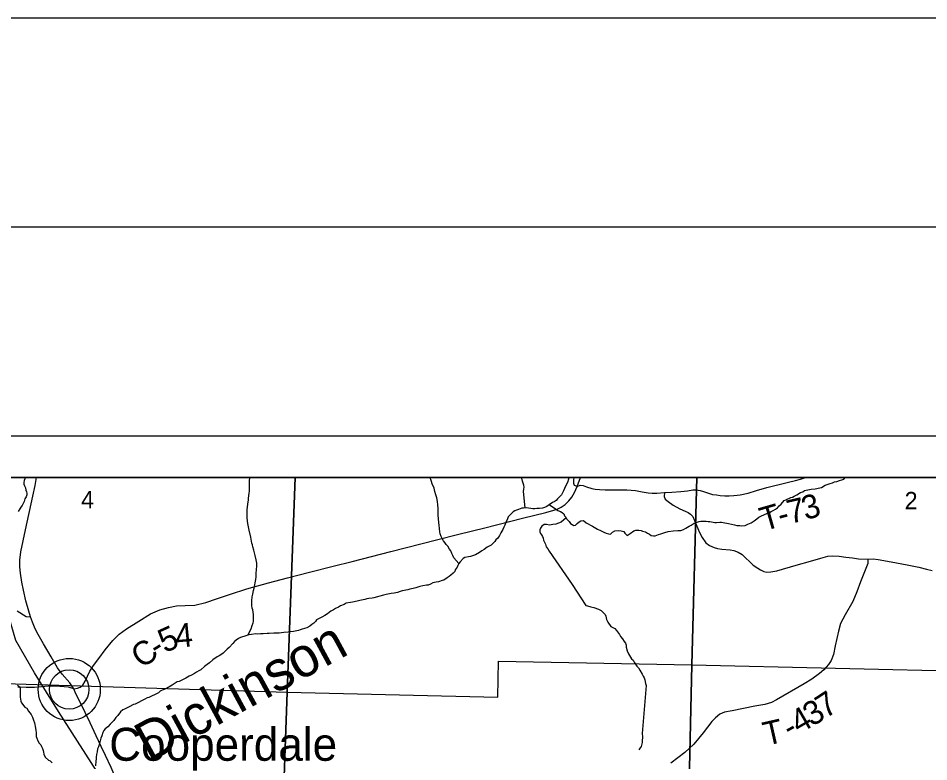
# Model space of a CAD drawing. Extents: x 0 to 34, y 0 to 22.
# Drawn here: x 3.454 to 5.636, y 20.219 to 22 of the extents above; entities that cross this region are included whole.
import ezdxf

# ---------------------------------------------------------------- set-up
doc = ezdxf.new("R2010")
doc.units = 0
for name, color, linetype in [('GM_X_Corporation', 7, 'Continuous'), ('GM_X_County_Road', 7, 'Continuous'), ('GM_X_County_Road_Text', 7, 'Continuous'), ('GM_X_Minor_River', 7, 'Continuous'), ('GM_X_Minor_River_Text', 7, 'Continuous'), ('GM_X_Rail_Line', 7, 'Continuous'), ('GM_X_Section_Text', 7, 'Continuous'), ('GM_X_State_Route', 7, 'Continuous'), ('GM_X_Township_Road', 7, 'Continuous'), ('GM_X_Township_Road_Text', 7, 'Continuous'), ('GM_X_Unincorporated', 7, 'Continuous'), ('GM_X_Unincorporated_Location', 7, 'Continuous'), ('GM_X_Unincorporated_Text', 7, 'Continuous'), ('SH_Border', 7, 'Continuous'), ('SH_Cut_Line', 7, 'Continuous'), ('SH_Data', 7, 'Continuous')]:
    doc.layers.add(name, color=color, linetype=linetype)

msp = doc.modelspace()

# ---------------------------------------------------------------- linework, layer by layer
at = {"layer": 'GM_X_Corporation'}
for points in [[(8.9, 20.9), (2.1, 20.9), (2.1, 16.4477), (2.1182, 16.4474), (2.1176, 16.4327), (2.1175, 16.4298), (2.1166, 16.4244), (2.1155, 16.4201), (2.2605, 16.4147), (2.3623, 16.41), (2.7707, 16.392), (3.0057, 16.3809), (3.6165, 16.3686), (3.7537, 16.3728), (3.9899, 16.3631), (4.4958, 16.358), (4.9914, 16.3477), (5.6931, 16.3352)], [(7.1302, 20.9), (2.2795, 20.9), (2.2346, 20.0021), (2.2301, 19.7293), (2.2185, 19.3474), (2.2174, 19.3106), (2.2173, 19.3051), (2.2163, 19.2747), (2.2155, 19.2474), (2.2151, 19.2353), (2.2075, 18.9201), (2.2042, 18.8835), (2.2038, 18.8576), (2.1995, 18.7384), (2.1894, 18.4715)]]:
    msp.add_lwpolyline(points, dxfattribs=at)
for points in [[(4.1178, 20.9), (3.125, 20.9), (3.1077, 20.4159), (4.0987, 20.3855)], [(5.08, 20.9), (4.1178, 20.9), (4.0987, 20.3855), (4.6031, 20.3739), (4.6046, 20.4596), (5.0677, 20.4508)], [(6.1094, 20.9), (5.08, 20.9), (5.0677, 20.4508), (6.1008, 20.4274)], [(4.0987, 20.3855), (4.6031, 20.3739), (4.6046, 20.4596), (5.0677, 20.4508), (5.0447, 19.4257), (4.5747, 19.4359), (4.5724, 19.3635), (4.0627, 19.3751)], [(6.1008, 20.4274), (6.0762, 19.405), (5.0447, 19.4257), (5.0677, 20.4508)], [(3.1077, 20.4159), (4.0987, 20.3855), (4.0627, 19.3751), (3.063, 19.4039)]]:
    msp.add_lwpolyline(points, close=True, dxfattribs=at)
at = {"layer": 'GM_X_County_Road'}
for points in [[(3.5871, 20.3938), (3.5961, 20.3949), (3.6021, 20.3975), (3.6084, 20.4028), (3.6144, 20.4123), (3.6257, 20.4357), (3.6345, 20.4493), (3.6474, 20.4663), (3.6625, 20.4868), (3.6808, 20.5097), (3.6959, 20.5248), (3.7136, 20.5374), (3.7426, 20.5561), (3.7711, 20.5731), (3.793, 20.5833), (3.814, 20.5887), (3.8335, 20.5921), (3.8543, 20.5933), (3.8772, 20.5941), (3.9036, 20.6005), (3.9288, 20.6093), (3.9629, 20.6203), (4.0014, 20.6329), (4.0538, 20.6478), (4.0994, 20.6593), (4.1518, 20.6729), (4.2084, 20.6873), (4.2541, 20.6984), (4.347, 20.7225), (4.4564, 20.7505), (4.5101, 20.7638), (4.5722, 20.7795), (4.6624, 20.8025), (4.7182, 20.8163), (4.7371, 20.8214), (4.745, 20.8238), (4.7546, 20.8288), (4.7649, 20.8355), (4.7735, 20.8439), (4.7804, 20.853), (4.7867, 20.8642), (4.7929, 20.8786), (4.8016, 20.8998), (4.8017, 20.9)], [(3.4517, 20.5803), (3.4734, 20.5669), (3.4834, 20.566)]]:
    msp.add_lwpolyline(points, dxfattribs=at)
at = {"layer": 'GM_X_Minor_River'}
for points in [[(3.4717, 20.9), (3.4701, 20.8967), (3.4682, 20.8925), (3.4678, 20.8876), (3.4678, 20.8838), (3.4694, 20.8796), (3.4716, 20.875)], [(4.004, 20.5221), (4.0118, 20.5371), (4.0148, 20.5451), (4.0167, 20.5516), (4.0174, 20.5553), (4.0178, 20.5607), (4.0178, 20.5652), (4.0174, 20.572), (4.0166, 20.5774), (4.0158, 20.583), (4.0147, 20.5872), (4.0139, 20.5933), (4.0135, 20.5982), (4.0135, 20.6047), (4.0146, 20.6138), (4.0161, 20.6206), (4.018, 20.6293), (4.0195, 20.635), (4.0206, 20.643), (4.0221, 20.6479), (4.0232, 20.6559), (4.0239, 20.6616), (4.0243, 20.6703), (4.025, 20.6798), (4.0254, 20.6874), (4.0254, 20.6946), (4.0242, 20.7026), (4.0219, 20.7132), (4.0188, 20.7257), (4.0158, 20.7337), (4.0154, 20.739), (4.0138, 20.7428), (4.0127, 20.747), (4.0112, 20.7572), (4.0073, 20.7739), (4.0058, 20.7815), (4.0042, 20.7898), (4.0031, 20.7955), (4.0023, 20.8042), (4.0023, 20.8111), (4.0026, 20.8221), (4.0034, 20.83), (4.0048, 20.8414), (4.0056, 20.8456), (4.006, 20.8505), (4.0074, 20.8623), (4.0078, 20.8668), (4.0082, 20.8718), (4.0085, 20.8839), (4.0085, 20.8915), (4.0092, 20.9)], [(4.51, 20.6936), (4.4978, 20.7076), (4.4951, 20.7133), (4.4929, 20.7175), (4.4902, 20.7243), (4.4871, 20.7284), (4.4833, 20.7353), (4.4795, 20.7391), (4.4761, 20.7444), (4.4727, 20.7485), (4.4696, 20.7538), (4.4677, 20.7584), (4.4654, 20.7652), (4.4639, 20.7694), (4.4631, 20.7777), (4.4623, 20.7861), (4.4616, 20.7914), (4.4608, 20.8013), (4.4604, 20.8088), (4.46, 20.8195), (4.46, 20.8259), (4.4592, 20.8346), (4.4584, 20.8422), (4.4568, 20.851), (4.4546, 20.8585), (4.4523, 20.8665), (4.4503, 20.8741), (4.4461, 20.8847), (4.4439, 20.8904), (4.4427, 20.8949), (4.4406, 20.9)], [(4.772, 20.9), (4.772, 20.8997), (4.7724, 20.8956), (4.7701, 20.888), (4.7656, 20.8788), (4.7629, 20.8739), (4.7607, 20.8682), (4.7581, 20.8629), (4.7558, 20.8587), (4.7524, 20.8549), (4.746, 20.8488), (4.7433, 20.845), (4.7384, 20.842), (4.7339, 20.8397), (4.7263, 20.8348), (4.7203, 20.8306), (4.715, 20.8283), (4.7104, 20.8268), (4.7028, 20.826), (4.6968, 20.8256), (4.6915, 20.8252), (4.6869, 20.8252), (4.6824, 20.8259), (4.671, 20.8271), (4.6649, 20.8267), (4.6604, 20.8263), (4.6528, 20.8236), (4.6479, 20.8217), (4.6437, 20.8198), (4.6396, 20.8175), (4.6328, 20.8107), (4.6283, 20.8054), (4.626, 20.8008), (4.6245, 20.797), (4.6226, 20.7932), (4.6196, 20.7856), (4.6177, 20.7811), (4.6151, 20.7754), (4.6128, 20.7716), (4.6106, 20.7674), (4.6072, 20.7609), (4.603, 20.7548), (4.5985, 20.7503), (4.5958, 20.7465), (4.5913, 20.7415), (4.5871, 20.7377), (4.5822, 20.7351), (4.5777, 20.7328), (4.5701, 20.7271), (4.5648, 20.724), (4.5592, 20.7202), (4.5493, 20.7149), (4.5425, 20.7126), (4.5376, 20.7107), (4.5327, 20.7099), (4.5243, 20.7084), (4.5202, 20.7057), (4.5126, 20.6981), (4.51, 20.6936)], [(4.6688, 20.8269), (4.6648, 20.8665), (4.6656, 20.8718), (4.6659, 20.8768), (4.6652, 20.8813), (4.664, 20.8866), (4.6625, 20.8912), (4.6609, 20.8984), (4.6604, 20.9)], [(5.3541, 20.8717), (5.3636, 20.8728), (5.3745, 20.8755), (5.3787, 20.8763), (5.3878, 20.8812), (5.3999, 20.8854), (5.4048, 20.8869), (5.4097, 20.8892), (5.4158, 20.8907), (5.4219, 20.8927), (5.4272, 20.8946), (5.4321, 20.8961), (5.4354, 20.9)], [(3.4716, 20.875), (3.4724, 20.8697), (3.4736, 20.8659), (3.4743, 20.8621), (3.4747, 20.8583), (3.4728, 20.8534), (3.4698, 20.8488), (3.468, 20.8424), (3.4657, 20.8375), (3.4631, 20.8329), (3.4604, 20.8287), (3.4582, 20.8249), (3.4536, 20.8181)], [(4.7266, 20.8349), (4.7411, 20.8245), (4.7468, 20.8208), (4.7533, 20.8181), (4.7574, 20.8158), (4.7612, 20.8128), (4.7631, 20.8083), (4.7662, 20.8045), (4.7688, 20.8003), (4.7738, 20.7942), (4.7776, 20.7901), (4.7814, 20.7871), (4.7852, 20.7852), (4.789, 20.7856), (4.7931, 20.7897), (4.798, 20.7935), (4.8022, 20.7962), (4.8086, 20.797), (4.8151, 20.7917), (4.8299, 20.783), (4.8417, 20.7762), (4.8493, 20.7728), (4.8568, 20.769), (4.8629, 20.7663), (4.8682, 20.7652), (4.8728, 20.7645), (4.8777, 20.769), (4.8834, 20.7721), (4.8917, 20.7728), (4.8985, 20.7721), (4.9053, 20.7706), (4.9076, 20.7664), (4.9129, 20.7611), (4.9201, 20.7661), (4.9288, 20.7718), (4.9338, 20.7741), (4.9413, 20.7741), (4.9463, 20.7726), (4.9501, 20.7714), (4.9569, 20.7696), (4.9618, 20.7665), (4.9664, 20.7639), (4.9705, 20.7612), (4.9762, 20.7601), (4.9804, 20.7605), (4.988, 20.7635), (4.9936, 20.7651), (4.9982, 20.7666), (5.0031, 20.7681), (5.0111, 20.7704), (5.0232, 20.772), (5.0345, 20.7731), (5.0417, 20.7731), (5.0478, 20.7754), (5.0535, 20.7785), (5.0618, 20.783), (5.0663, 20.7861), (5.0739, 20.7907), (5.0853, 20.7945), (5.0898, 20.7949), (5.094, 20.7952), (5.1027, 20.7949), (5.1072, 20.7945), (5.1114, 20.7945), (5.119, 20.7926), (5.1232, 20.7919), (5.1273, 20.7919), (5.1349, 20.7927), (5.1391, 20.7931), (5.1432, 20.7919), (5.1558, 20.7901), (5.1705, 20.7867), (5.1759, 20.7852), (5.1827, 20.7848), (5.1872, 20.7844), (5.1956, 20.7852), (5.202, 20.7879), (5.2103, 20.7913), (5.2171, 20.7959), (5.2239, 20.8012), (5.2285, 20.8046), (5.233, 20.8073), (5.2421, 20.8111), (5.2481, 20.8138), (5.2542, 20.8161), (5.2584, 20.8183), (5.2633, 20.821), (5.2686, 20.8237), (5.2731, 20.8275), (5.2773, 20.8317), (5.2818, 20.8362), (5.2894, 20.8446), (5.2935, 20.8465), (5.3049, 20.8518), (5.309, 20.8526), (5.3136, 20.8553), (5.32, 20.8587), (5.3287, 20.8636), (5.334, 20.8659), (5.3382, 20.8686), (5.3541, 20.8717)], [(4.7669, 20.8033), (4.7548, 20.7927), (4.7484, 20.7904), (4.7424, 20.7885), (4.7348, 20.7873), (4.7268, 20.7858), (4.7196, 20.7873), (4.7143, 20.7877), (4.709, 20.7831), (4.7056, 20.7789), (4.7041, 20.7744), (4.7038, 20.7698), (4.7053, 20.766), (4.7079, 20.7622), (4.7102, 20.7585), (4.7118, 20.7547), (4.7125, 20.7501), (4.7141, 20.7463), (4.7175, 20.7399), (4.7194, 20.7338), (4.7232, 20.7289), (4.7262, 20.7236), (4.7814, 20.6436), (4.8142, 20.5936), (4.8179, 20.5921), (4.8263, 20.5898), (4.8335, 20.5883), (4.8445, 20.5849), (4.8506, 20.5815), (4.8551, 20.5777), (4.8601, 20.5721), (4.862, 20.5679), (4.8639, 20.5595), (4.8666, 20.5535), (4.8742, 20.5432), (4.8833, 20.538), (4.8875, 20.5338), (4.892, 20.5273), (4.8947, 20.5236), (4.8974, 20.519), (4.9023, 20.5133), (4.9057, 20.5073), (4.9095, 20.5027), (4.9107, 20.4985), (4.9111, 20.4932), (4.913, 20.4849), (4.9164, 20.4773), (4.9233, 20.4659), (4.9271, 20.4622), (4.9297, 20.4572), (4.9366, 20.4481), (4.9404, 20.4436), (4.9434, 20.4387), (4.9488, 20.4288), (4.9511, 20.4243), (4.9537, 20.4197), (4.9556, 20.4155), (4.9572, 20.4064), (4.9583, 20.4019), (4.9492, 20.2865), (4.9496, 20.2789), (4.9492, 20.2687), (4.9489, 20.2649), (4.9466, 20.2558), (4.944, 20.252), (4.941, 20.2478)], [(4.51, 20.6936), (4.507, 20.6894), (4.5058, 20.6848), (4.5013, 20.6784), (4.4998, 20.6746), (4.496, 20.6704), (4.4904, 20.6662), (4.4862, 20.6624), (4.4817, 20.6594), (4.4741, 20.6541), (4.4699, 20.6529), (4.4608, 20.6499), (4.4552, 20.6491), (4.4476, 20.6472), (4.4415, 20.6445), (4.4359, 20.6422), (4.4321, 20.6418), (4.4234, 20.6407), (4.4165, 20.6388), (4.4071, 20.6353), (4.4003, 20.6342), (4.3927, 20.6327), (4.3874, 20.6308), (4.3741, 20.6281), (4.3692, 20.6265), (4.3624, 20.6246), (4.3548, 20.6231), (4.3476, 20.622), (4.3355, 20.6197), (4.3291, 20.6181), (4.3204, 20.6155), (4.3147, 20.6139), (4.3064, 20.6116), (4.3022, 20.6109), (4.2939, 20.6101), (4.2893, 20.6089), (4.2848, 20.6078), (4.2723, 20.6055), (4.2658, 20.604), (4.2549, 20.6009), (4.2499, 20.6005), (4.2401, 20.5986), (4.2348, 20.5959), (4.2265, 20.5925), (4.2212, 20.5895), (4.214, 20.586), (4.2094, 20.583), (4.2034, 20.5796), (4.1989, 20.5762), (4.1947, 20.5731), (4.1886, 20.5697), (4.1811, 20.5651), (4.1735, 20.5613), (4.1686, 20.559), (4.166, 20.5552), (4.1622, 20.551), (4.1576, 20.548), (4.1527, 20.5438), (4.1455, 20.5396), (4.1342, 20.537), (4.1296, 20.5347), (4.1255, 20.5335), (4.1175, 20.5316), (4.1134, 20.5309), (4.1043, 20.5301), (4.1005, 20.5297), (4.0903, 20.5285), (4.0796, 20.5274), (4.0706, 20.527), (4.0668, 20.527), (4.0554, 20.5266), (4.0505, 20.5262), (4.0406, 20.5258), (4.0349, 20.5254), (4.0274, 20.525), (4.0232, 20.5254), (4.0126, 20.5238), (4.0065, 20.5227), (3.999, 20.5208), (3.9865, 20.5166), (3.9815, 20.5143), (3.9763, 20.5105), (3.9721, 20.5071), (3.9683, 20.5025), (3.9596, 20.493), (3.9547, 20.4885), (3.9491, 20.4835), (3.9449, 20.4793), (3.9392, 20.4751), (3.9351, 20.4729), (3.9309, 20.4702), (3.9203, 20.463), (3.912, 20.4561), (3.9067, 20.4516), (3.9007, 20.447), (3.8916, 20.4394), (3.8867, 20.4367), (3.8814, 20.4333), (3.8761, 20.4303), (3.8689, 20.4268), (3.8632, 20.4238)], [(3.8632, 20.4238), (3.8553, 20.4192), (3.8398, 20.4112), (3.8352, 20.4101), (3.8231, 20.4021), (3.8091, 20.3945), (3.8038, 20.3918), (3.7989, 20.3907), (3.7944, 20.388), (3.7902, 20.3842), (3.7807, 20.3796), (3.7747, 20.377), (3.7667, 20.3728), (3.763, 20.3724), (3.7577, 20.369), (3.7342, 20.3572), (3.73, 20.356), (3.7198, 20.3503), (3.7085, 20.345), (3.7043, 20.3435), (3.699, 20.3385), (3.6926, 20.3302), (3.6881, 20.3248), (3.6828, 20.318), (3.6741, 20.3093), (3.6688, 20.3028), (3.6624, 20.2975), (3.659, 20.2937), (3.6567, 20.2891), (3.6545, 20.2811), (3.6522, 20.2758), (3.6503, 20.2694), (3.6488, 20.2637), (3.6477, 20.2599), (3.6462, 20.2546), (3.6443, 20.25), (3.6428, 20.2428), (3.6417, 20.2367), (3.641, 20.2303), (3.6406, 20.2261), (3.6399, 20.2204), (3.6388, 20.209)], [(3.4526, 20.4022), (3.4567, 20.3996), (3.4583, 20.3954), (3.4583, 20.3798), (3.4587, 20.3734), (3.4602, 20.3643), (3.4618, 20.3601), (3.4701, 20.3499), (3.4743, 20.3472), (3.4789, 20.3404), (3.485, 20.3324), (3.488, 20.3256)], [(3.488, 20.3256), (3.4907, 20.3184), (3.4926, 20.3123), (3.4934, 20.3086), (3.4949, 20.3036), (3.4964, 20.2949), (3.4968, 20.2884), (3.4968, 20.2839), (3.4972, 20.2793), (3.4988, 20.2752), (3.5011, 20.2695), (3.5045, 20.2634), (3.5079, 20.2592), (3.5098, 20.2555), (3.5125, 20.2505), (3.5136, 20.246), (3.5148, 20.2418), (3.5156, 20.2369), (3.5182, 20.2304), (3.5262, 20.2232), (3.5308, 20.221), (3.5353, 20.2164)]]:
    msp.add_lwpolyline(points, dxfattribs=at)
at = {"layer": 'GM_X_Rail_Line'}
msp.add_lwpolyline([(4.8515, 18.4096), (4.468, 18.9077), (4.382, 19.0334), (4.1748, 19.3749), (3.8527, 19.8843), (3.6877, 20.1234), (3.6615, 20.1661), (3.5505, 20.339), (3.4927, 20.4317), (3.4483, 20.5097), (3.4202, 20.6049), (3.4057, 20.6941), (3.4068, 20.7593), (3.4191, 20.8537), (3.4357, 20.9)], dxfattribs=at)
at = {"layer": 'GM_X_State_Route'}
for points in [[(3.4834, 20.566), (3.4792, 20.5799), (3.4725, 20.6042), (3.4667, 20.6299), (3.463, 20.6495), (3.4593, 20.6706), (3.4579, 20.6856), (3.4582, 20.7021), (3.4602, 20.7222), (3.4712, 20.7744), (3.4889, 20.8553), (3.4943, 20.8805), (3.4981, 20.9)], [(3.6265, 20.3119), (3.6144, 20.3373), (3.5908, 20.3854), (3.5871, 20.3938), (3.5776, 20.4077), (3.5591, 20.429), (3.5484, 20.444), (3.5332, 20.4702), (3.5149, 20.5014), (3.5019, 20.5236), (3.4947, 20.5373), (3.4878, 20.5537), (3.4834, 20.566)], [(3.684, 20.1883), (3.6767, 20.2051), (3.6628, 20.2338), (3.6528, 20.2558), (3.6408, 20.2813), (3.6313, 20.3019), (3.6265, 20.3119)]]:
    msp.add_lwpolyline(points, dxfattribs=at)
at = {"layer": 'GM_X_Township_Road'}
for points in [[(4.7929, 20.8786), (4.7871, 20.8807), (4.785, 20.8857), (4.7855, 20.8936), (4.7865, 20.9)], [(4.7929, 20.8786), (4.8003, 20.8814), (4.8075, 20.881), (4.8154, 20.8779), (4.8286, 20.8738), (4.8362, 20.8719), (4.847, 20.8712), (4.8601, 20.8702), (4.8905, 20.8702), (4.9123, 20.87), (4.9329, 20.8688), (4.9489, 20.8654), (4.9638, 20.863), (4.9729, 20.8621), (4.9844, 20.8621), (5.0026, 20.8637), (5.0205, 20.8649), (5.0416, 20.8664), (5.0579, 20.8678), (5.0708, 20.87), (5.0784, 20.87), (5.0878, 20.869), (5.0957, 20.8664), (5.1055, 20.863), (5.1172, 20.8594), (5.127, 20.858), (5.1356, 20.8566), (5.1474, 20.8563), (5.1577, 20.8561), (5.1687, 20.8566), (5.1768, 20.8575), (5.1835, 20.8587), (5.2028, 20.8621), (5.2228, 20.8691), (5.248, 20.8758), (5.2667, 20.8811), (5.2773, 20.8835), (5.2999, 20.8888), (5.3165, 20.8929), (5.3285, 20.8957), (5.336, 20.8981), (5.3407, 20.9)], [(5.0026, 20.8637), (5.0014, 20.8544), (5.004, 20.8479), (5.0117, 20.8422), (5.0236, 20.8336), (5.0392, 20.8247), (5.0519, 20.8195), (5.0593, 20.8161), (5.0648, 20.8118), (5.0701, 20.8061), (5.0748, 20.797), (5.0866, 20.7685), (5.0926, 20.7565), (5.1017, 20.7436), (5.11, 20.7371), (5.1215, 20.7319), (5.1299, 20.7295), (5.1399, 20.7283), (5.1596, 20.7266), (5.1687, 20.7249), (5.179, 20.7211), (5.1883, 20.7151), (5.2151, 20.69), (5.2259, 20.6828), (5.2323, 20.679), (5.2402, 20.6749), (5.2474, 20.6735), (5.2575, 20.6739), (5.2714, 20.6763), (5.3183, 20.6897), (5.3525, 20.6995), (5.3769, 20.707), (5.3937, 20.7118), (5.4063, 20.7122), (5.4207, 20.7118), (5.437, 20.7094), (5.4533, 20.7072), (5.4676, 20.705), (5.4899, 20.7043), (5.5023, 20.7048), (5.5143, 20.7034), (5.5459, 20.6976), (5.5844, 20.6907), (5.6122, 20.6852), (5.6306, 20.6804), (5.644, 20.6768)], [(5.4899, 20.7043), (5.4894, 20.6938), (5.4719, 20.6502), (5.4635, 20.6261), (5.454, 20.6028), (5.4351, 20.5713), (5.4245, 20.5502), (5.4195, 20.5322), (5.4119, 20.4963), (5.4075, 20.476), (5.402, 20.4616), (5.3956, 20.4516), (5.3846, 20.4394), (5.3738, 20.4303), (5.3554, 20.4171), (5.3369, 20.4053), (5.2712, 20.367), (5.2587, 20.3606), (5.2433, 20.3563), (5.2194, 20.3518), (5.1646, 20.341), (5.1462, 20.3374), (5.1352, 20.3329), (5.1244, 20.3245), (5.1158, 20.3151), (5.095, 20.2886), (5.0729, 20.2615), (5.0509, 20.2412), (5.0176, 20.2153)], [(3.5871, 20.3938), (3.5741, 20.3979), (3.5431, 20.3998), (3.5179, 20.3991), (3.4933, 20.3972), (3.4727, 20.3969), (3.4533, 20.3975)]]:
    msp.add_lwpolyline(points, dxfattribs=at)
at = {"layer": 'GM_X_Unincorporated'}
for radius in [0.0744, 0.0472]:
    msp.add_circle((3.5763, 20.3922), radius, dxfattribs=at)
at = {"layer": 'GM_X_Unincorporated_Location'}
msp.add_line((3.5763, 20.3922), (3.5763, 20.3922), dxfattribs=at)
at = {"layer": 'SH_Border'}
msp.add_lwpolyline([(1.5, 21.5), (33.5, 21.5), (33.5, 0.5), (1.5, 0.5)], close=True, dxfattribs=at)
at = {"layer": 'SH_Cut_Line'}
msp.add_lwpolyline([(0, 0), (34, 0), (34, 22), (0, 22)], close=True, dxfattribs=at)
at = {"layer": 'SH_Data'}
for p, q in [((2, 21), (9, 21)), ((2.1, 20.9), (8.9, 20.9))]:
    msp.add_line(p, q, dxfattribs=at)

# ---------------------------------------------------------------- texts
at = {"layer": 'GM_X_County_Road_Text'}
for s, rotation, p in [('5', 24.2837, (3.8052, 20.4787)), ('4', 5.3, (3.8323, 20.4918)), ('C', 36.1502, (3.7504, 20.4405)), ('-', 31.6372, (3.7871, 20.4674))]:
    msp.add_text(s, height=0.0568, rotation=rotation, dxfattribs=at).set_placement(p)
at = {"layer": 'GM_X_Minor_River_Text'}
msp.add_text('Dickinson', height=0.09467, rotation=28.4668, dxfattribs=at).set_placement((3.7674, 20.2166))
at = {"layer": 'GM_X_Section_Text'}
for s, p in [('4', (3.6046, 20.826)), ('2', (5.5779, 20.8235))]:
    msp.add_text(s, height=0.0419, rotation=0, dxfattribs=at).set_placement(p)
at = {"layer": 'GM_X_Township_Road_Text'}
for s, rotation, p in [('3', 16.2693, (5.3405, 20.7973)), ('T', 16.0843, (5.2405, 20.771)), ('7', 13.1034, (5.3031, 20.7885)), ('-', 14.7519, (5.281, 20.7826)), ('7', 33.018, (5.3881, 20.3214)), ('3', 30.381, (5.3554, 20.3022)), ('4', 30.1105, (5.3249, 20.2845)), ('T', 12.8086, (5.2458, 20.2569)), ('-', 29.3132, (5.3038, 20.2727))]:
    msp.add_text(s, height=0.0568, rotation=rotation, dxfattribs=at).set_placement(p)
at = {"layer": 'GM_X_Unincorporated_Text'}
msp.add_text('Cooperdale', height=0.07898, rotation=0, dxfattribs=at).set_placement((3.6721, 20.2214))

doc.saveas('drawing.dxf')
